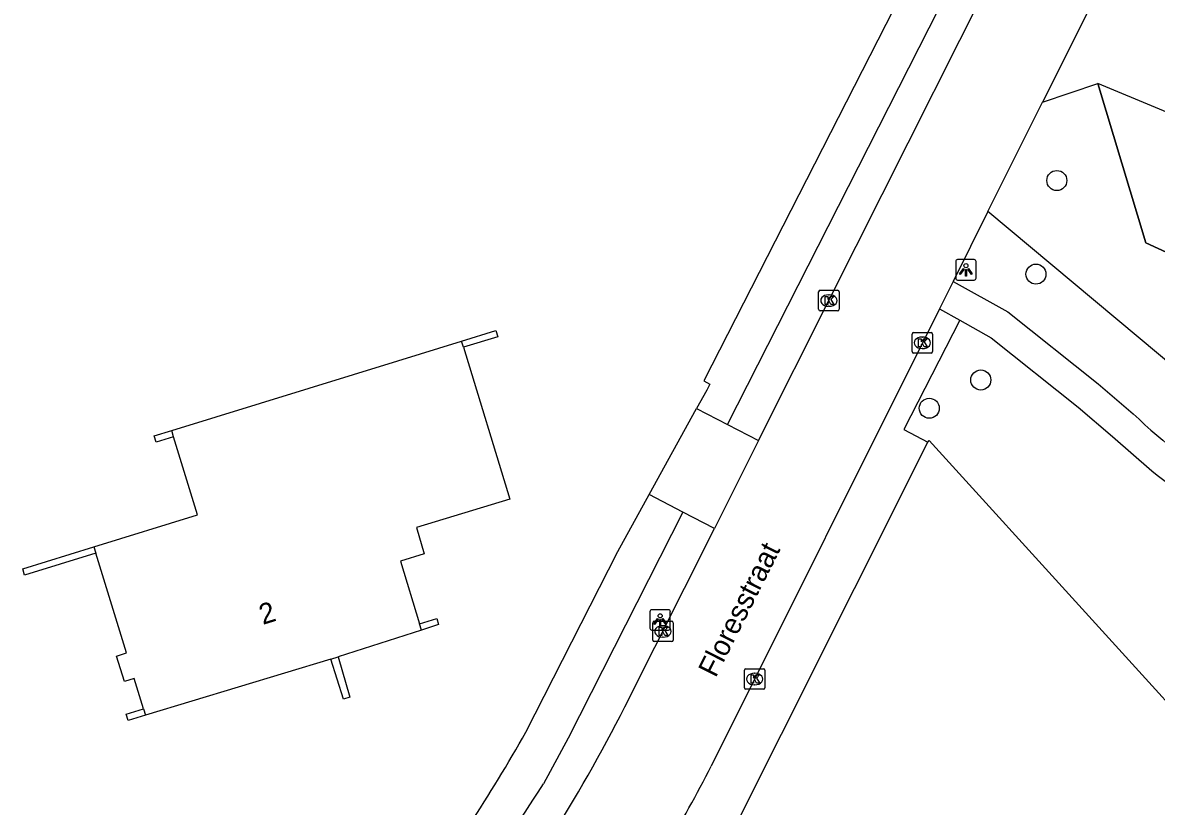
# Model space of a CAD drawing. Extents: x 162417 to 163721, y 384268 to 385416.
# Drawn here: x 163414.6 to 163470, y 384656 to 384694.2 of the extents above; entities that cross this region are included whole.
import ezdxf

# ---------------------------------------------------------------- set-up
doc = ezdxf.new("R2010")
doc.units = 0
for name, color, linetype in [('IMGEO_Berm_groen', 7, 'Continuous'), ('IMGEO_Boom', 7, 'Continuous'), ('IMGEO_Groenvoorziening', 7, 'Continuous'), ('IMGEO_Hek', 7, 'Continuous'), ('IMGEO_Kolk', 7, 'Continuous'), ('IMGEO_Lichtpunt', 7, 'Continuous'), ('IMGEO_Muur', 7, 'Continuous'), ('IMGEO_Openbare_ruimte_label', 7, 'Continuous'), ('IMGEO_Pand', 7, 'Continuous'), ('IMGEO_Pand_nummerreeks', 7, 'Continuous'), ('IMGEO_Rijbaan_lokaal_open', 7, 'Continuous'), ('IMGEO_Voetpad_halfverhard', 7, 'Continuous'), ('IMGEO_Voetpad_open', 7, 'Continuous')]:
    doc.layers.add(name, color=color, linetype=linetype)

msp = doc.modelspace()

# ---------------------------------------------------------------- linework, layer by layer
at = {"layer": 'IMGEO_Berm_groen'}
for points in [[(163473.287, 384675.375), (163461.78, 384684.985)], [(163460.408, 384679.673), (163457.666, 384674.338), (163458.848, 384673.73)], [(163458.848, 384673.73), (163458.908, 384673.806), (163474.172, 384657.022)]]:
    msp.add_lwpolyline(points, dxfattribs=at)
at = {"layer": 'IMGEO_Boom'}
for centre in [(163465.141, 384686.493), (163464.123, 384681.926), (163461.429, 384676.762), (163458.914, 384675.383)]:
    msp.add_circle(centre, 0.489, dxfattribs=at)
at = {"layer": 'IMGEO_Groenvoorziening'}
for points in [[(163580.363, 384712.213), (163500, 384688.721), (163484.237, 384684.113), (163467.143, 384691.226)], [(163464.448, 384690.322), (163467.143, 384691.226)], [(163467.143, 384691.226), (163469.49, 384683.461), (163479.995, 384678.63)], [(163445.562, 384648.482), (163448.112, 384652.334), (163458.848, 384673.73)]]:
    msp.add_lwpolyline(points, dxfattribs=at)
at = {"layer": 'IMGEO_Hek'}
for points in [[(163479.995, 384678.63), (163469.49, 384683.461), (163467.143, 384691.226)], [(163458.848, 384673.73), (163458.908, 384673.806), (163474.172, 384657.022)]]:
    msp.add_lwpolyline(points, dxfattribs=at)
at = {"layer": 'IMGEO_Kolk'}
for p, q in [((163453.511, 384680.211), (163453.511, 384681.063)), ((163453.586, 384681.137), (163454.438, 384681.137)), ((163453.999, 384680.917), (163454.024, 384680.917)), ((163454.512, 384681.063), (163454.512, 384680.211)), ((163454.438, 384680.137), (163453.586, 384680.137)), ((163454.022, 384680.357), (163453.997, 384680.357)), ((163458.073, 384678.15), (163458.073, 384679.002)), ((163458.148, 384679.076), (163459, 384679.076)), ((163459.074, 384679.002), (163459.074, 384678.15)), ((163458.561, 384678.856), (163458.586, 384678.856)), ((163459, 384678.076), (163458.148, 384678.076)), ((163458.584, 384678.296), (163458.559, 384678.296)), ((163445.408, 384664.069), (163445.408, 384664.921)), ((163445.483, 384664.995), (163446.335, 384664.995)), ((163445.896, 384664.775), (163445.921, 384664.775)), ((163446.409, 384664.921), (163446.409, 384664.069)), ((163445.919, 384664.215), (163445.894, 384664.215)), ((163446.335, 384663.995), (163445.483, 384663.995)), ((163449.888, 384661.744), (163449.888, 384662.596)), ((163449.963, 384662.67), (163450.815, 384662.67)), ((163450.376, 384662.45), (163450.401, 384662.45)), ((163450.889, 384662.596), (163450.889, 384661.744)), ((163450.399, 384661.89), (163450.374, 384661.89)), ((163450.815, 384661.67), (163449.963, 384661.67))]:
    msp.add_line(p, q, dxfattribs=at)
for points in [[(163453.511, 384680.211), (163453.511, 384681.063)], [(163453.586, 384681.137), (163454.438, 384681.137)], [(163453.832, 384680.837), (163453.955, 384680.837), (163453.955, 384680.686), (163454.085, 384680.837), (163454.249, 384680.837), (163454.103, 384680.686), (163454.256, 384680.437), (163454.104, 384680.437), (163454.019, 384680.601), (163453.955, 384680.534), (163453.955, 384680.437), (163453.832, 384680.437), (163453.832, 384680.837)], [(163454.512, 384681.063), (163454.512, 384680.211)], [(163454.438, 384680.137), (163453.586, 384680.137)], [(163458.073, 384678.15), (163458.073, 384679.002)], [(163458.148, 384679.076), (163459, 384679.076)], [(163459.074, 384679.002), (163459.074, 384678.15)], [(163458.394, 384678.776), (163458.517, 384678.776), (163458.517, 384678.625), (163458.647, 384678.776), (163458.811, 384678.776), (163458.665, 384678.625), (163458.818, 384678.376), (163458.666, 384678.376), (163458.581, 384678.54), (163458.517, 384678.473), (163458.517, 384678.376), (163458.394, 384678.376), (163458.394, 384678.776)], [(163459, 384678.076), (163458.148, 384678.076)], [(163445.408, 384664.069), (163445.408, 384664.921)], [(163445.483, 384664.995), (163446.335, 384664.995)], [(163445.729, 384664.695), (163445.852, 384664.695), (163445.852, 384664.544), (163445.982, 384664.695), (163446.146, 384664.695), (163446, 384664.544), (163446.153, 384664.295), (163446.001, 384664.295), (163445.916, 384664.459), (163445.852, 384664.392), (163445.852, 384664.295), (163445.729, 384664.295), (163445.729, 384664.695)], [(163446.409, 384664.921), (163446.409, 384664.069)], [(163446.335, 384663.995), (163445.483, 384663.995)], [(163449.888, 384661.744), (163449.888, 384662.596)], [(163449.963, 384662.67), (163450.815, 384662.67)], [(163450.209, 384662.37), (163450.332, 384662.37), (163450.332, 384662.219), (163450.462, 384662.37), (163450.626, 384662.37), (163450.48, 384662.219), (163450.633, 384661.97), (163450.481, 384661.97), (163450.396, 384662.134), (163450.332, 384662.067), (163450.332, 384661.97), (163450.209, 384661.97), (163450.209, 384662.37)], [(163450.889, 384662.596), (163450.889, 384661.744)], [(163450.815, 384661.67), (163449.963, 384661.67)]]:
    msp.add_lwpolyline(points, dxfattribs=at)
for centre, start, end in [((163453.588, 384681.061), 91.552, 178.448), ((163453.588, 384681.061), 91.552, 178.448), ((163454.436, 384681.061), 1.552, 88.448), ((163454.436, 384681.061), 1.552, 88.448), ((163453.588, 384680.213), 181.552, 268.448), ((163453.588, 384680.213), 181.552, 268.448), ((163454.436, 384680.213), 271.552, 358.448), ((163454.436, 384680.213), 271.552, 358.448), ((163458.15, 384679), 91.552, 178.448), ((163458.15, 384679), 91.552, 178.448), ((163458.998, 384679), 1.552, 88.448), ((163458.998, 384679), 1.552, 88.448), ((163458.15, 384678.152), 181.552, 268.448), ((163458.15, 384678.152), 181.552, 268.448), ((163458.998, 384678.152), 271.552, 358.448), ((163458.998, 384678.152), 271.552, 358.448), ((163445.485, 384664.919), 91.552, 178.448), ((163445.485, 384664.919), 91.552, 178.448), ((163446.333, 384664.919), 1.552, 88.448), ((163446.333, 384664.919), 1.552, 88.448), ((163445.485, 384664.071), 181.552, 268.448), ((163445.485, 384664.071), 181.552, 268.448), ((163446.333, 384664.071), 271.552, 358.448), ((163446.333, 384664.071), 271.552, 358.448), ((163449.965, 384662.594), 91.552, 178.448), ((163449.965, 384662.594), 91.552, 178.448), ((163450.813, 384662.594), 1.552, 88.448), ((163450.813, 384662.594), 1.552, 88.448), ((163449.965, 384661.746), 181.552, 268.448), ((163449.965, 384661.746), 181.552, 268.448), ((163450.813, 384661.746), 271.552, 358.448), ((163450.813, 384661.746), 271.552, 358.448)]:
    msp.add_arc(centre, 0.0765, start, end, dxfattribs=at)
for centre, major_axis, ratio, start_param, end_param in [((163453.998, 384680.637), (-0.387, 0.002), 0.722429, 4.712389, 7.853982), ((163454.023, 384680.637), (-0.39, 0.002), 0.717154, 1.570796, 4.712389), ((163458.56, 384678.576), (-0.387, 0.002), 0.722429, 4.712389, 7.853982), ((163458.585, 384678.576), (-0.39, 0.002), 0.717154, 1.570796, 4.712389), ((163445.895, 384664.495), (-0.387, 0.002), 0.722429, 4.712389, 7.853982), ((163445.92, 384664.495), (-0.39, 0.002), 0.717154, 1.570796, 4.712389), ((163450.375, 384662.17), (-0.387, 0.002), 0.722429, 4.712389, 7.853982), ((163450.4, 384662.17), (-0.39, 0.002), 0.717154, 1.570796, 4.712389)]:
    msp.add_ellipse(centre, major_axis=major_axis, ratio=ratio, start_param=start_param, end_param=end_param, dxfattribs=at)
at = {"layer": 'IMGEO_Lichtpunt'}
for p, q in [((163460.204, 384682.54), (163460.204, 384681.733)), ((163460.204, 384682.54), (163460.204, 384681.733)), ((163461.106, 384682.635), (163460.298, 384682.635)), ((163461.106, 384682.635), (163460.298, 384682.635)), ((163461.2, 384681.733), (163461.2, 384682.54)), ((163461.2, 384681.733), (163461.2, 384682.54)), ((163460.298, 384681.639), (163461.106, 384681.639)), ((163460.298, 384681.639), (163461.106, 384681.639)), ((163445.274, 384665.458), (163445.274, 384664.651)), ((163445.274, 384665.458), (163445.274, 384664.651)), ((163446.176, 384665.553), (163445.368, 384665.553)), ((163446.176, 384665.553), (163445.368, 384665.553)), ((163446.27, 384664.651), (163446.27, 384665.458)), ((163446.27, 384664.651), (163446.27, 384665.458)), ((163445.368, 384664.557), (163446.176, 384664.557)), ((163445.368, 384664.557), (163446.176, 384664.557))]:
    msp.add_line(p, q, dxfattribs=at)
for points in [[(163460.578, 384682.204), (163460.617, 384682.176), (163460.429, 384681.914), (163460.391, 384681.941), (163460.578, 384682.204)], [(163460.68, 384682.156), (163460.727, 384682.156), (163460.727, 384681.834), (163460.68, 384681.834), (163460.68, 384682.156)], [(163460.79, 384682.176), (163460.828, 384682.203), (163461.015, 384681.941), (163460.976, 384681.913), (163460.79, 384682.176)], [(163445.648, 384665.122), (163445.687, 384665.094), (163445.499, 384664.832), (163445.461, 384664.859), (163445.648, 384665.122)], [(163445.75, 384665.074), (163445.797, 384665.074), (163445.797, 384664.752), (163445.75, 384664.752), (163445.75, 384665.074)], [(163445.86, 384665.094), (163445.898, 384665.121), (163446.085, 384664.859), (163446.046, 384664.831), (163445.86, 384665.094)]]:
    msp.add_lwpolyline(points, dxfattribs=at)
for centre in [(163460.703, 384682.338), (163445.773, 384665.256)]:
    msp.add_circle(centre, 0.0994, dxfattribs=at)
for centre, start, end in [((163460.298, 384682.54), 90, 180), ((163460.298, 384682.54), 90, 180), ((163461.106, 384682.54), 0, 90), ((163461.106, 384682.54), 0, 90), ((163460.298, 384681.733), 180, 270), ((163460.298, 384681.733), 180, 270), ((163461.106, 384681.733), 270, 0), ((163461.106, 384681.733), 270, 360), ((163445.368, 384665.458), 90, 180), ((163445.368, 384665.458), 90, 180), ((163446.176, 384665.458), 0, 90), ((163446.176, 384665.458), 0, 90), ((163445.368, 384664.651), 180, 270), ((163445.368, 384664.651), 180, 270), ((163446.176, 384664.651), 270, 0), ((163446.176, 384664.651), 270, 360)]:
    msp.add_arc(centre, 0.0946, start, end, dxfattribs=at)
at = {"layer": 'IMGEO_Muur'}
for points in [[(163436.081, 384678.656), (163437.751, 384679.17), (163437.85, 384678.867), (163436.172, 384678.357)], [(163422.018, 384673.996), (163421.159, 384673.732), (163421.066, 384674.038), (163421.924, 384674.302)], [(163418.215, 384668.311), (163414.741, 384667.243), (163414.648, 384667.55), (163418.121, 384668.618)], [(163434.022, 384664.858), (163434.875, 384665.118), (163434.957, 384664.826), (163434.113, 384664.556)], [(163430.056, 384663.259), (163430.618, 384661.287), (163430.317, 384661.195), (163429.702, 384663.147)], [(163420.642, 384660.41), (163419.8, 384660.155), (163419.706, 384660.462), (163420.547, 384660.72)]]:
    msp.add_lwpolyline(points, dxfattribs=at)
at = {"layer": 'IMGEO_Pand'}
for points in [[(163421.924, 384674.302), (163432.972, 384677.7), (163436.081, 384678.656)], [(163436.172, 384678.357), (163436.081, 384678.656)], [(163436.172, 384678.357), (163438.427, 384670.953), (163433.875, 384669.56), (163434.243, 384668.287), (163433.093, 384667.922), (163434.022, 384664.858)], [(163418.121, 384668.618), (163423.191, 384670.177), (163422.018, 384673.996)], [(163422.018, 384673.996), (163421.924, 384674.302)], [(163418.121, 384668.618), (163418.215, 384668.311)], [(163420.547, 384660.72), (163420.093, 384662.199), (163419.616, 384662.053), (163419.235, 384663.295), (163419.712, 384663.442), (163418.215, 384668.311)], [(163434.113, 384664.556), (163434.022, 384664.858)], [(163434.113, 384664.556), (163430.056, 384663.259)], [(163429.702, 384663.147), (163420.642, 384660.41)], [(163429.702, 384663.147), (163430.056, 384663.259)], [(163420.547, 384660.72), (163420.642, 384660.41)]]:
    msp.add_lwpolyline(points, dxfattribs=at)
at = {"layer": 'IMGEO_Rijbaan_lokaal_open'}
for points in [[(163450.578, 384673.812), (163454.071, 384680.764), (163464.216, 384700.914)], [(163469.126, 384699.679), (163464.448, 384690.322)], [(163461.78, 384684.985), (163464.448, 384690.322)], [(163461.78, 384684.985), (163460.076, 384681.575)], [(163460.076, 384681.575), (163459.405, 384680.232)], [(163459.405, 384680.232), (163448.271, 384657.924)], [(163450.578, 384673.812), (163448.42, 384669.517)], [(163444.048, 384660.817), (163448.42, 384669.517)]]:
    msp.add_lwpolyline(points, dxfattribs=at)
for centre, radius, start, end in [((163372.322, 384697.23), 80.439, 327.69017, 333.08477), ((163370.348, 384698.203), 87.718, 326.61785, 332.66515)]:
    msp.add_arc(centre, radius, start, end, dxfattribs=at)
at = {"layer": 'IMGEO_Voetpad_halfverhard'}
for points in [[(163460.076, 384681.575), (163462.751, 384680.085), (163467.155, 384676.576), (163468.874, 384675.113)], [(163459.405, 384680.232), (163460.408, 384679.673)], [(163460.408, 384679.673), (163461.935, 384678.823), (163466.183, 384675.435), (163467.865, 384674.003), (163469.772, 384672.33)]]:
    msp.add_lwpolyline(points, dxfattribs=at)
for centre, radius, start, end in [((163485.513, 384692.199), 23.849, 225.7581, 255.4999), ((163485.475, 384692.116), 25.26, 231.5634, 255.5506)]:
    msp.add_arc(centre, radius, start, end, dxfattribs=at)
at = {"layer": 'IMGEO_Voetpad_open'}
for points in [[(163456.356, 384725.796), (163457.241, 384724.223), (163465.046, 384710.362), (163461.604, 384703.558), (163462.377, 384703.14), (163461.429, 384701.275), (163460.651, 384701.67), (163447.906, 384676.713), (163448.203, 384676.553), (163448.047, 384676.269), (163447.549, 384675.363)], [(163449.056, 384674.591), (163467.268, 384710.395)], [(163445.245, 384671.173), (163447.549, 384675.363)], [(163447.549, 384675.363), (163449.056, 384674.591)], [(163449.056, 384674.591), (163450.578, 384673.812)], [(163439.207, 384659.583), (163443.713, 384668.387), (163445.245, 384671.173)], [(163446.884, 384670.318), (163445.245, 384671.173)], [(163446.884, 384670.318), (163441.276, 384659.294), (163440.077, 384657.063)], [(163448.42, 384669.517), (163446.884, 384670.318)]]:
    msp.add_lwpolyline(points, dxfattribs=at)
for centre, radius, start, end in [((163383.007, 384690.738), 64.258, 321.562, 330.99773), ((163349.96, 384713.846), 106.515, 323.65813, 327.78495)]:
    msp.add_arc(centre, radius, start, end, dxfattribs=at)

# ---------------------------------------------------------------- texts
at = {"layer": 'IMGEO_Openbare_ruimte_label'}
msp.add_text('Floresstraat', height=1, rotation=63.2556, dxfattribs=at).set_placement((163448.482, 384662.195))
at = {"layer": 'IMGEO_Pand_nummerreeks'}
msp.add_text('2', height=1, rotation=17.1085, dxfattribs=at).set_placement((163426.373, 384664.81))

doc.saveas('drawing.dxf')
